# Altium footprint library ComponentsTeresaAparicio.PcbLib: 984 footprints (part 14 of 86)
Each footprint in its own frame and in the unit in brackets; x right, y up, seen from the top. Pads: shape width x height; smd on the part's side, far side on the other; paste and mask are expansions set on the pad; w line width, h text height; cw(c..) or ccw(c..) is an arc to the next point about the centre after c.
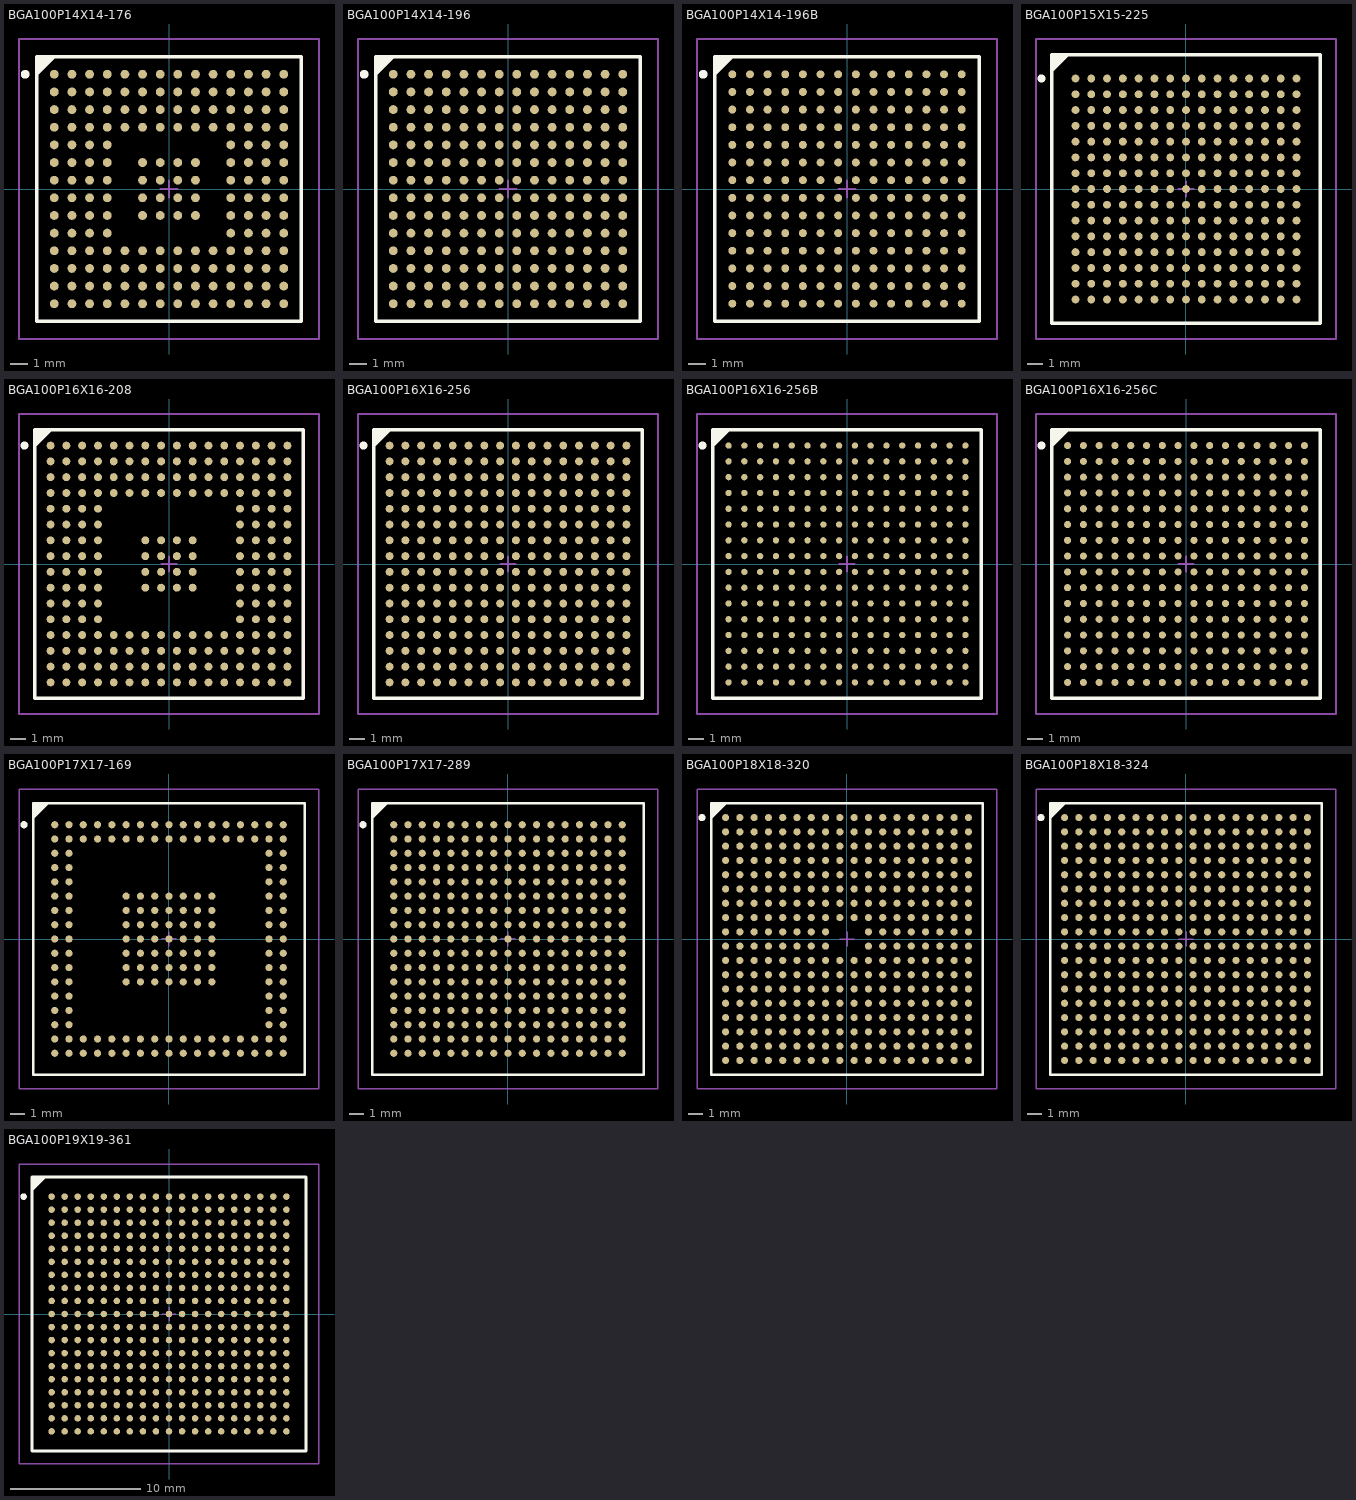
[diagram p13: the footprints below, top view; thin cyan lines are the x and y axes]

## BGA100P14X14-176 [mm] "BGA, 176-Leads, Body 15x15mm, Pitch 1mm"
height 2.05
pads (176):
  round 0.5 smd: A1(-6.5,6.5) A2(-5.5,6.5) A3(-4.5,6.5) A4(-3.5,6.5) A5(-2.5,6.5) A6(-1.5,6.5) A7(-0.5,6.5) A8(0.5,6.5) A9(1.5,6.5) A10(2.5,6.5) A11(3.5,6.5) A12(4.5,6.5) A13(5.5,6.5) A14(6.5,6.5) B1(-6.5,5.5) B2(-5.5,5.5) B3(-4.5,5.5) B4(-3.5,5.5) B5(-2.5,5.5) B6(-1.5,5.5) B7(-0.5,5.5) B8(0.5,5.5) B9(1.5,5.5) B10(2.5,5.5) B11(3.5,5.5) B12(4.5,5.5) B13(5.5,5.5) B14(6.5,5.5) C1(-6.5,4.5) C2(-5.5,4.5) C3(-4.5,4.5) C4(-3.5,4.5) C5(-2.5,4.5) C6(-1.5,4.5) C7(-0.5,4.5) C8(0.5,4.5) C9(1.5,4.5) C10(2.5,4.5) C11(3.5,4.5) C12(4.5,4.5) C13(5.5,4.5) C14(6.5,4.5) D1(-6.5,3.5) D2(-5.5,3.5) D3(-4.5,3.5) D4(-3.5,3.5) D5(-2.5,3.5) D6(-1.5,3.5) D7(-0.5,3.5) D8(0.5,3.5) D9(1.5,3.5) D10(2.5,3.5) D11(3.5,3.5) D12(4.5,3.5) D13(5.5,3.5) D14(6.5,3.5) E1(-6.5,2.5) E2(-5.5,2.5) E3(-4.5,2.5) E4(-3.5,2.5) E11(3.5,2.5) E12(4.5,2.5) E13(5.5,2.5) E14(6.5,2.5) F1(-6.5,1.5) F2(-5.5,1.5) F3(-4.5,1.5) F4(-3.5,1.5) F6(-1.5,1.5) F7(-0.5,1.5) F8(0.5,1.5) F9(1.5,1.5) F11(3.5,1.5) F12(4.5,1.5) F13(5.5,1.5) F14(6.5,1.5) G1(-6.5,0.5) G2(-5.5,0.5) G3(-4.5,0.5) G4(-3.5,0.5) G6(-1.5,0.5) G7(-0.5,0.5) G8(0.5,0.5) G9(1.5,0.5) G11(3.5,0.5) G12(4.5,0.5) G13(5.5,0.5) G14(6.5,0.5) H1(-6.5,-0.5) H2(-5.5,-0.5) H3(-4.5,-0.5) H4(-3.5,-0.5) H6(-1.5,-0.5) H7(-0.5,-0.5) H8(0.5,-0.5) H9(1.5,-0.5) H11(3.5,-0.5) H12(4.5,-0.5) H13(5.5,-0.5) H14(6.5,-0.5) J1(-6.5,-1.5) J2(-5.5,-1.5) J3(-4.5,-1.5) J4(-3.5,-1.5) J6(-1.5,-1.5) J7(-0.5,-1.5) J8(0.5,-1.5) J9(1.5,-1.5) J11(3.5,-1.5) J12(4.5,-1.5) J13(5.5,-1.5) J14(6.5,-1.5) K1(-6.5,-2.5) K2(-5.5,-2.5) K3(-4.5,-2.5) K4(-3.5,-2.5) K11(3.5,-2.5) K12(4.5,-2.5) K13(5.5,-2.5) K14(6.5,-2.5) L1(-6.5,-3.5) L2(-5.5,-3.5) L3(-4.5,-3.5) L4(-3.5,-3.5) L5(-2.5,-3.5) L6(-1.5,-3.5) L7(-0.5,-3.5) L8(0.5,-3.5) L9(1.5,-3.5) L10(2.5,-3.5) L11(3.5,-3.5) L12(4.5,-3.5) L13(5.5,-3.5) L14(6.5,-3.5) M1(-6.5,-4.5) M2(-5.5,-4.5) M3(-4.5,-4.5) M4(-3.5,-4.5) M5(-2.5,-4.5) M6(-1.5,-4.5) M7(-0.5,-4.5) M8(0.5,-4.5) M9(1.5,-4.5) M10(2.5,-4.5) M11(3.5,-4.5) M12(4.5,-4.5) M13(5.5,-4.5) M14(6.5,-4.5) N1(-6.5,-5.5) N2(-5.5,-5.5) N3(-4.5,-5.5) N4(-3.5,-5.5) N5(-2.5,-5.5) N6(-1.5,-5.5) N7(-0.5,-5.5) N8(0.5,-5.5) N9(1.5,-5.5) N10(2.5,-5.5) N11(3.5,-5.5) N12(4.5,-5.5) N13(5.5,-5.5) N14(6.5,-5.5) P1(-6.5,-6.5) P2(-5.5,-6.5) P3(-4.5,-6.5) P4(-3.5,-6.5) P5(-2.5,-6.5) P6(-1.5,-6.5) P7(-0.5,-6.5) P8(0.5,-6.5) P9(1.5,-6.5) P10(2.5,-6.5) P11(3.5,-6.5) P12(4.5,-6.5) P13(5.5,-6.5) P14(6.5,-6.5)
Top Overlay:
  circle w0.25: c-8.15,6.5 r0.125
  region: -6.5,7.5 -7.5,6.5 -7.5,7.5
  lines w0.2: -7.5,6.5 -6.5,7.5 ; -7.5,-7.5 -7.5,7.5 7.5,7.5 7.5,-7.5 -7.5,-7.5
Mechanical 13:
  lines w0.1: -7.5,-7.5 -7.5,7.5 7.5,7.5 7.5,-7.5 -7.5,-7.5
Mechanical 15:
  lines w0.1: -0.5,0 0.5,0 ; 0,-0.5 0,0.5 ; -8.5,-8.5 -8.5,8.5 8.5,8.5 8.5,-8.5 -8.5,-8.5
3D body: height 0, standoff 0, extent -7.5,-7.5 7.5,7.5

## BGA100P14X14-196 [mm] "BGA, 196-Leads, Body 15x15mm, Pitch 1mm"
height 1.9
pads (196):
  round 0.5 smd: A1(-6.5,6.5) A2(-5.5,6.5) A3(-4.5,6.5) A4(-3.5,6.5) A5(-2.5,6.5) A6(-1.5,6.5) A7(-0.5,6.5) A8(0.5,6.5) A9(1.5,6.5) A10(2.5,6.5) A11(3.5,6.5) A12(4.5,6.5) A13(5.5,6.5) A14(6.5,6.5) B1(-6.5,5.5) B2(-5.5,5.5) B3(-4.5,5.5) B4(-3.5,5.5) B5(-2.5,5.5) B6(-1.5,5.5) B7(-0.5,5.5) B8(0.5,5.5) B9(1.5,5.5) B10(2.5,5.5) B11(3.5,5.5) B12(4.5,5.5) B13(5.5,5.5) B14(6.5,5.5) C1(-6.5,4.5) C2(-5.5,4.5) C3(-4.5,4.5) C4(-3.5,4.5) C5(-2.5,4.5) C6(-1.5,4.5) C7(-0.5,4.5) C8(0.5,4.5) C9(1.5,4.5) C10(2.5,4.5) C11(3.5,4.5) C12(4.5,4.5) C13(5.5,4.5) C14(6.5,4.5) D1(-6.5,3.5) D2(-5.5,3.5) D3(-4.5,3.5) D4(-3.5,3.5) D5(-2.5,3.5) D6(-1.5,3.5) D7(-0.5,3.5) D8(0.5,3.5) D9(1.5,3.5) D10(2.5,3.5) D11(3.5,3.5) D12(4.5,3.5) D13(5.5,3.5) D14(6.5,3.5) E1(-6.5,2.5) E2(-5.5,2.5) E3(-4.5,2.5) E4(-3.5,2.5) E5(-2.5,2.5) E6(-1.5,2.5) E7(-0.5,2.5) E8(0.5,2.5) E9(1.5,2.5) E10(2.5,2.5) E11(3.5,2.5) E12(4.5,2.5) E13(5.5,2.5) E14(6.5,2.5) F1(-6.5,1.5) F2(-5.5,1.5) F3(-4.5,1.5) F4(-3.5,1.5) F5(-2.5,1.5) F6(-1.5,1.5) F7(-0.5,1.5) F8(0.5,1.5) F9(1.5,1.5) F10(2.5,1.5) F11(3.5,1.5) F12(4.5,1.5) F13(5.5,1.5) F14(6.5,1.5) G1(-6.5,0.5) G2(-5.5,0.5) G3(-4.5,0.5) G4(-3.5,0.5) G5(-2.5,0.5) G6(-1.5,0.5) G7(-0.5,0.5) G8(0.5,0.5) G9(1.5,0.5) G10(2.5,0.5) G11(3.5,0.5) G12(4.5,0.5) G13(5.5,0.5) G14(6.5,0.5) H1(-6.5,-0.5) H2(-5.5,-0.5) H3(-4.5,-0.5) H4(-3.5,-0.5) H5(-2.5,-0.5) H6(-1.5,-0.5) H7(-0.5,-0.5) H8(0.5,-0.5) H9(1.5,-0.5) H10(2.5,-0.5) H11(3.5,-0.5) H12(4.5,-0.5) H13(5.5,-0.5) H14(6.5,-0.5) J1(-6.5,-1.5) J2(-5.5,-1.5) J3(-4.5,-1.5) J4(-3.5,-1.5) J5(-2.5,-1.5) J6(-1.5,-1.5) J7(-0.5,-1.5) J8(0.5,-1.5) J9(1.5,-1.5) J10(2.5,-1.5) J11(3.5,-1.5) J12(4.5,-1.5) J13(5.5,-1.5) J14(6.5,-1.5) K1(-6.5,-2.5) K2(-5.5,-2.5) K3(-4.5,-2.5) K4(-3.5,-2.5) K5(-2.5,-2.5) K6(-1.5,-2.5) K7(-0.5,-2.5) K8(0.5,-2.5) K9(1.5,-2.5) K10(2.5,-2.5) K11(3.5,-2.5) K12(4.5,-2.5) K13(5.5,-2.5) K14(6.5,-2.5) L1(-6.5,-3.5) L2(-5.5,-3.5) L3(-4.5,-3.5) L4(-3.5,-3.5) L5(-2.5,-3.5) L6(-1.5,-3.5) L7(-0.5,-3.5) L8(0.5,-3.5) L9(1.5,-3.5) L10(2.5,-3.5) L11(3.5,-3.5) L12(4.5,-3.5) L13(5.5,-3.5) L14(6.5,-3.5) M1(-6.5,-4.5) M2(-5.5,-4.5) M3(-4.5,-4.5) M4(-3.5,-4.5) M5(-2.5,-4.5) M6(-1.5,-4.5) M7(-0.5,-4.5) M8(0.5,-4.5) M9(1.5,-4.5) M10(2.5,-4.5) M11(3.5,-4.5) M12(4.5,-4.5) M13(5.5,-4.5) M14(6.5,-4.5) N1(-6.5,-5.5) N2(-5.5,-5.5) N3(-4.5,-5.5) N4(-3.5,-5.5) N5(-2.5,-5.5) N6(-1.5,-5.5) N7(-0.5,-5.5) N8(0.5,-5.5) N9(1.5,-5.5) N10(2.5,-5.5) N11(3.5,-5.5) N12(4.5,-5.5) N13(5.5,-5.5) N14(6.5,-5.5) P1(-6.5,-6.5) P2(-5.5,-6.5) P3(-4.5,-6.5) P4(-3.5,-6.5) P5(-2.5,-6.5) P6(-1.5,-6.5) P7(-0.5,-6.5) P8(0.5,-6.5) P9(1.5,-6.5) P10(2.5,-6.5) P11(3.5,-6.5) P12(4.5,-6.5) P13(5.5,-6.5) P14(6.5,-6.5)
Top Overlay:
  circle w0.25: c-8.15,6.5 r0.125
  region: -6.5,7.5 -7.5,6.5 -7.5,7.5
  lines w0.2: -7.5,6.5 -6.5,7.5 ; -7.5,-7.5 -7.5,7.5 7.5,7.5 7.5,-7.5 -7.5,-7.5
Mechanical 13:
  lines w0.1: -7.5,-7.5 -7.5,7.5 7.5,7.5 7.5,-7.5 -7.5,-7.5
Mechanical 15:
  lines w0.1: -0.5,0 0.5,0 ; 0,-0.5 0,0.5 ; -8.5,-8.5 -8.5,8.5 8.5,8.5 8.5,-8.5 -8.5,-8.5
3D body: height 0, standoff 0, extent -7.5,-7.5 7.5,7.5

## BGA100P14X14-196B [mm] "BGA, 196-Leads, Body 15x15mm, Pitch 1mm"
height 1.7
pads (196):
  round 0.45 smd: A1(-6.5,6.5) A2(-5.5,6.5) A3(-4.5,6.5) A4(-3.5,6.5) A5(-2.5,6.5) A6(-1.5,6.5) A7(-0.5,6.5) A8(0.5,6.5) A9(1.5,6.5) A10(2.5,6.5) A11(3.5,6.5) A12(4.5,6.5) A13(5.5,6.5) A14(6.5,6.5) B1(-6.5,5.5) B2(-5.5,5.5) B3(-4.5,5.5) B4(-3.5,5.5) B5(-2.5,5.5) B6(-1.5,5.5) B7(-0.5,5.5) B8(0.5,5.5) B9(1.5,5.5) B10(2.5,5.5) B11(3.5,5.5) B12(4.5,5.5) B13(5.5,5.5) B14(6.5,5.5) C1(-6.5,4.5) C2(-5.5,4.5) C3(-4.5,4.5) C4(-3.5,4.5) C5(-2.5,4.5) C6(-1.5,4.5) C7(-0.5,4.5) C8(0.5,4.5) C9(1.5,4.5) C10(2.5,4.5) C11(3.5,4.5) C12(4.5,4.5) C13(5.5,4.5) C14(6.5,4.5) D1(-6.5,3.5) D2(-5.5,3.5) D3(-4.5,3.5) D4(-3.5,3.5) D5(-2.5,3.5) D6(-1.5,3.5) D7(-0.5,3.5) D8(0.5,3.5) D9(1.5,3.5) D10(2.5,3.5) D11(3.5,3.5) D12(4.5,3.5) D13(5.5,3.5) D14(6.5,3.5) E1(-6.5,2.5) E2(-5.5,2.5) E3(-4.5,2.5) E4(-3.5,2.5) E5(-2.5,2.5) E6(-1.5,2.5) E7(-0.5,2.5) E8(0.5,2.5) E9(1.5,2.5) E10(2.5,2.5) E11(3.5,2.5) E12(4.5,2.5) E13(5.5,2.5) E14(6.5,2.5) F1(-6.5,1.5) F2(-5.5,1.5) F3(-4.5,1.5) F4(-3.5,1.5) F5(-2.5,1.5) F6(-1.5,1.5) F7(-0.5,1.5) F8(0.5,1.5) F9(1.5,1.5) F10(2.5,1.5) F11(3.5,1.5) F12(4.5,1.5) F13(5.5,1.5) F14(6.5,1.5) G1(-6.5,0.5) G2(-5.5,0.5) G3(-4.5,0.5) G4(-3.5,0.5) G5(-2.5,0.5) G6(-1.5,0.5) G7(-0.5,0.5) G8(0.5,0.5) G9(1.5,0.5) G10(2.5,0.5) G11(3.5,0.5) G12(4.5,0.5) G13(5.5,0.5) G14(6.5,0.5) H1(-6.5,-0.5) H2(-5.5,-0.5) H3(-4.5,-0.5) H4(-3.5,-0.5) H5(-2.5,-0.5) H6(-1.5,-0.5) H7(-0.5,-0.5) H8(0.5,-0.5) H9(1.5,-0.5) H10(2.5,-0.5) H11(3.5,-0.5) H12(4.5,-0.5) H13(5.5,-0.5) H14(6.5,-0.5) J1(-6.5,-1.5) J2(-5.5,-1.5) J3(-4.5,-1.5) J4(-3.5,-1.5) J5(-2.5,-1.5) J6(-1.5,-1.5) J7(-0.5,-1.5) J8(0.5,-1.5) J9(1.5,-1.5) J10(2.5,-1.5) J11(3.5,-1.5) J12(4.5,-1.5) J13(5.5,-1.5) J14(6.5,-1.5) K1(-6.5,-2.5) K2(-5.5,-2.5) K3(-4.5,-2.5) K4(-3.5,-2.5) K5(-2.5,-2.5) K6(-1.5,-2.5) K7(-0.5,-2.5) K8(0.5,-2.5) K9(1.5,-2.5) K10(2.5,-2.5) K11(3.5,-2.5) K12(4.5,-2.5) K13(5.5,-2.5) K14(6.5,-2.5) L1(-6.5,-3.5) L2(-5.5,-3.5) L3(-4.5,-3.5) L4(-3.5,-3.5) L5(-2.5,-3.5) L6(-1.5,-3.5) L7(-0.5,-3.5) L8(0.5,-3.5) L9(1.5,-3.5) L10(2.5,-3.5) L11(3.5,-3.5) L12(4.5,-3.5) L13(5.5,-3.5) L14(6.5,-3.5) M1(-6.5,-4.5) M2(-5.5,-4.5) M3(-4.5,-4.5) M4(-3.5,-4.5) M5(-2.5,-4.5) M6(-1.5,-4.5) M7(-0.5,-4.5) M8(0.5,-4.5) M9(1.5,-4.5) M10(2.5,-4.5) M11(3.5,-4.5) M12(4.5,-4.5) M13(5.5,-4.5) M14(6.5,-4.5) N1(-6.5,-5.5) N2(-5.5,-5.5) N3(-4.5,-5.5) N4(-3.5,-5.5) N5(-2.5,-5.5) N6(-1.5,-5.5) N7(-0.5,-5.5) N8(0.5,-5.5) N9(1.5,-5.5) N10(2.5,-5.5) N11(3.5,-5.5) N12(4.5,-5.5) N13(5.5,-5.5) N14(6.5,-5.5) P1(-6.5,-6.5) P2(-5.5,-6.5) P3(-4.5,-6.5) P4(-3.5,-6.5) P5(-2.5,-6.5) P6(-1.5,-6.5) P7(-0.5,-6.5) P8(0.5,-6.5) P9(1.5,-6.5) P10(2.5,-6.5) P11(3.5,-6.5) P12(4.5,-6.5) P13(5.5,-6.5) P14(6.5,-6.5)
Top Overlay:
  circle w0.25: c-8.15,6.5 r0.125
  region: -6.5,7.5 -7.5,6.5 -7.5,7.5
  lines w0.2: -7.5,6.5 -6.5,7.5 ; -7.5,-7.5 -7.5,7.5 7.5,7.5 7.5,-7.5 -7.5,-7.5
Mechanical 13:
  lines w0.1: -7.5,-7.5 -7.5,7.5 7.5,7.5 7.5,-7.5 -7.5,-7.5
Mechanical 15:
  lines w0.1: -0.5,0 0.5,0 ; 0,-0.5 0,0.5 ; -8.5,-8.5 -8.5,8.5 8.5,8.5 8.5,-8.5 -8.5,-8.5
3D body: height 1.7, standoff 0, extent -7.5,-7.5 7.5,7.5

## BGA100P15X15-225 [mm] "BGA, 225-Leads, Body 17x17mm, Pitch 1mm"
height 3.5
pads (225):
  round 0.5 smd: A1(-7,7) A2(-6,7) A3(-5,7) A4(-4,7) A5(-3,7) A6(-2,7) A7(-1,7) A8(0,7) A9(1,7) A10(2,7) A11(3,7) A12(4,7) A13(5,7) A14(6,7) A15(7,7) B1(-7,6) B2(-6,6) B3(-5,6) B4(-4,6) B5(-3,6) B6(-2,6) B7(-1,6) B8(0,6) B9(1,6) B10(2,6) B11(3,6) B12(4,6) B13(5,6) B14(6,6) B15(7,6) C1(-7,5) C2(-6,5) C3(-5,5) C4(-4,5) C5(-3,5) C6(-2,5) C7(-1,5) C8(0,5) C9(1,5) C10(2,5) C11(3,5) C12(4,5) C13(5,5) C14(6,5) C15(7,5) D1(-7,4) D2(-6,4) D3(-5,4) D4(-4,4) D5(-3,4) D6(-2,4) D7(-1,4) D8(0,4) D9(1,4) D10(2,4) D11(3,4) D12(4,4) D13(5,4) D14(6,4) D15(7,4) E1(-7,3) E2(-6,3) E3(-5,3) E4(-4,3) E5(-3,3) E6(-2,3) E7(-1,3) E8(0,3) E9(1,3) E10(2,3) E11(3,3) E12(4,3) E13(5,3) E14(6,3) E15(7,3) F1(-7,2) F2(-6,2) F3(-5,2) F4(-4,2) F5(-3,2) F6(-2,2) F7(-1,2) F8(0,2) F9(1,2) F10(2,2) F11(3,2) F12(4,2) F13(5,2) F14(6,2) F15(7,2) G1(-7,1) G2(-6,1) G3(-5,1) G4(-4,1) G5(-3,1) G6(-2,1) G7(-1,1) G8(0,1) G9(1,1) G10(2,1) G11(3,1) G12(4,1) G13(5,1) G14(6,1) G15(7,1) H1(-7,0) H2(-6,0) H3(-5,0) H4(-4,0) H5(-3,0) H6(-2,0) H7(-1,0) H8(0,0) H9(1,0) H10(2,0) H11(3,0) H12(4,0) H13(5,0) H14(6,0) H15(7,0) J1(-7,-1) J2(-6,-1) J3(-5,-1) J4(-4,-1) J5(-3,-1) J6(-2,-1) J7(-1,-1) J8(0,-1) J9(1,-1) J10(2,-1) J11(3,-1) J12(4,-1) J13(5,-1) J14(6,-1) J15(7,-1) K1(-7,-2) K2(-6,-2) K3(-5,-2) K4(-4,-2) K5(-3,-2) K6(-2,-2) K7(-1,-2) K8(0,-2) K9(1,-2) K10(2,-2) K11(3,-2) K12(4,-2) K13(5,-2) K14(6,-2) K15(7,-2) L1(-7,-3) L2(-6,-3) L3(-5,-3) L4(-4,-3) L5(-3,-3) L6(-2,-3) L7(-1,-3) L8(0,-3) L9(1,-3) L10(2,-3) L11(3,-3) L12(4,-3) L13(5,-3) L14(6,-3) L15(7,-3) M1(-7,-4) M2(-6,-4) M3(-5,-4) M4(-4,-4) M5(-3,-4) M6(-2,-4) M7(-1,-4) M8(0,-4) M9(1,-4) M10(2,-4) M11(3,-4) M12(4,-4) M13(5,-4) M14(6,-4) M15(7,-4) N1(-7,-5) N2(-6,-5) N3(-5,-5) N4(-4,-5) N5(-3,-5) N6(-2,-5) N7(-1,-5) N8(0,-5) N9(1,-5) N10(2,-5) N11(3,-5) N12(4,-5) N13(5,-5) N14(6,-5) N15(7,-5) P1(-7,-6) P2(-6,-6) P3(-5,-6) P4(-4,-6) P5(-3,-6) P6(-2,-6) P7(-1,-6) P8(0,-6) P9(1,-6) P10(2,-6) P11(3,-6) P12(4,-6) P13(5,-6) P14(6,-6) P15(7,-6) R1(-7,-7) R2(-6,-7) R3(-5,-7) R4(-4,-7) R5(-3,-7) R6(-2,-7) R7(-1,-7) R8(0,-7) R9(1,-7) R10(2,-7) R11(3,-7) R12(4,-7) R13(5,-7) R14(6,-7) R15(7,-7)
Top Overlay:
  circle w0.25: c-9.15,7 r0.125
  region: -7.5,8.5 -8.5,7.5 -8.5,8.5
  lines w0.2: -8.5,7.5 -7.5,8.5 ; -8.5,-8.5 8.5,-8.5 8.5,8.5 -8.5,8.5 -8.5,-8.5
Mechanical 13:
  lines w0.1: -8.5,-8.5 8.5,-8.5 8.5,8.5 -8.5,8.5 -8.5,-8.5
Mechanical 15:
  lines w0.1: -0.5,0 0.5,0 ; 0,-0.5 0,0.5 ; -9.5,-9.5 9.5,-9.5 9.5,9.5 -9.5,9.5 -9.5,-9.5
3D body: height 0, standoff 0, extent -8.5,-8.5 8.5,8.5

## BGA100P16X16-208 [mm] "BGA, 208-Leads, Body 17x17mm, Pitch 1mm"
height 2.1
pads (208):
  round 0.5 smd: A1(-7.5,7.5) A2(-6.5,7.5) A3(-5.5,7.5) A4(-4.5,7.5) A5(-3.5,7.5) A6(-2.5,7.5) A7(-1.5,7.5) A8(-0.5,7.5) A9(0.5,7.5) A10(1.5,7.5) A11(2.5,7.5) A12(3.5,7.5) A13(4.5,7.5) A14(5.5,7.5) A15(6.5,7.5) A16(7.5,7.5) B1(-7.5,6.5) B2(-6.5,6.5) B3(-5.5,6.5) B4(-4.5,6.5) B5(-3.5,6.5) B6(-2.5,6.5) B7(-1.5,6.5) B8(-0.5,6.5) B9(0.5,6.5) B10(1.5,6.5) B11(2.5,6.5) B12(3.5,6.5) B13(4.5,6.5) B14(5.5,6.5) B15(6.5,6.5) B16(7.5,6.5) C1(-7.5,5.5) C2(-6.5,5.5) C3(-5.5,5.5) C4(-4.5,5.5) C5(-3.5,5.5) C6(-2.5,5.5) C7(-1.5,5.5) C8(-0.5,5.5) C9(0.5,5.5) C10(1.5,5.5) C11(2.5,5.5) C12(3.5,5.5) C13(4.5,5.5) C14(5.5,5.5) C15(6.5,5.5) C16(7.5,5.5) D1(-7.5,4.5) D2(-6.5,4.5) D3(-5.5,4.5) D4(-4.5,4.5) D5(-3.5,4.5) D6(-2.5,4.5) D7(-1.5,4.5) D8(-0.5,4.5) D9(0.5,4.5) D10(1.5,4.5) D11(2.5,4.5) D12(3.5,4.5) D13(4.5,4.5) D14(5.5,4.5) D15(6.5,4.5) D16(7.5,4.5) E1(-7.5,3.5) E2(-6.5,3.5) E3(-5.5,3.5) E4(-4.5,3.5) E13(4.5,3.5) E14(5.5,3.5) E15(6.5,3.5) E16(7.5,3.5) F1(-7.5,2.5) F2(-6.5,2.5) F3(-5.5,2.5) F4(-4.5,2.5) F13(4.5,2.5) F14(5.5,2.5) F15(6.5,2.5) F16(7.5,2.5) G1(-7.5,1.5) G2(-6.5,1.5) G3(-5.5,1.5) G4(-4.5,1.5) G7(-1.5,1.5) G8(-0.5,1.5) G9(0.5,1.5) G10(1.5,1.5) G13(4.5,1.5) G14(5.5,1.5) G15(6.5,1.5) G16(7.5,1.5) H1(-7.5,0.5) H2(-6.5,0.5) H3(-5.5,0.5) H4(-4.5,0.5) H7(-1.5,0.5) H8(-0.5,0.5) H9(0.5,0.5) H10(1.5,0.5) H13(4.5,0.5) H14(5.5,0.5) H15(6.5,0.5) H16(7.5,0.5) J1(-7.5,-0.5) J2(-6.5,-0.5) J3(-5.5,-0.5) J4(-4.5,-0.5) J7(-1.5,-0.5) J8(-0.5,-0.5) J9(0.5,-0.5) J10(1.5,-0.5) J13(4.5,-0.5) J14(5.5,-0.5) J15(6.5,-0.5) J16(7.5,-0.5) K1(-7.5,-1.5) K2(-6.5,-1.5) K3(-5.5,-1.5) K4(-4.5,-1.5) K7(-1.5,-1.5) K8(-0.5,-1.5) K9(0.5,-1.5) K10(1.5,-1.5) K13(4.5,-1.5) K14(5.5,-1.5) K15(6.5,-1.5) K16(7.5,-1.5) L1(-7.5,-2.5) L2(-6.5,-2.5) L3(-5.5,-2.5) L4(-4.5,-2.5) L13(4.5,-2.5) L14(5.5,-2.5) L15(6.5,-2.5) L16(7.5,-2.5) M1(-7.5,-3.5) M2(-6.5,-3.5) M3(-5.5,-3.5) M4(-4.5,-3.5) M13(4.5,-3.5) M14(5.5,-3.5) M15(6.5,-3.5) M16(7.5,-3.5) N1(-7.5,-4.5) N2(-6.5,-4.5) N3(-5.5,-4.5) N4(-4.5,-4.5) N5(-3.5,-4.5) N6(-2.5,-4.5) N7(-1.5,-4.5) N8(-0.5,-4.5) N9(0.5,-4.5) N10(1.5,-4.5) N11(2.5,-4.5) N12(3.5,-4.5) N13(4.5,-4.5) N14(5.5,-4.5) N15(6.5,-4.5) N16(7.5,-4.5) P1(-7.5,-5.5) P2(-6.5,-5.5) P3(-5.5,-5.5) P4(-4.5,-5.5) P5(-3.5,-5.5) P6(-2.5,-5.5) P7(-1.5,-5.5) P8(-0.5,-5.5) P9(0.5,-5.5) P10(1.5,-5.5) P11(2.5,-5.5) P12(3.5,-5.5) P13(4.5,-5.5) P14(5.5,-5.5) P15(6.5,-5.5) P16(7.5,-5.5) R1(-7.5,-6.5) R2(-6.5,-6.5) R3(-5.5,-6.5) R4(-4.5,-6.5) R5(-3.5,-6.5) R6(-2.5,-6.5) R7(-1.5,-6.5) R8(-0.5,-6.5) R9(0.5,-6.5) R10(1.5,-6.5) R11(2.5,-6.5) R12(3.5,-6.5) R13(4.5,-6.5) R14(5.5,-6.5) R15(6.5,-6.5) R16(7.5,-6.5) T1(-7.5,-7.5) T2(-6.5,-7.5) T3(-5.5,-7.5) T4(-4.5,-7.5) T5(-3.5,-7.5) T6(-2.5,-7.5) T7(-1.5,-7.5) T8(-0.5,-7.5) T9(0.5,-7.5) T10(1.5,-7.5) T11(2.5,-7.5) T12(3.5,-7.5) T13(4.5,-7.5) T14(5.5,-7.5) T15(6.5,-7.5) T16(7.5,-7.5)
Top Overlay:
  circle w0.25: c-9.15,7.5 r0.125
  region: -7.5,8.5 -8.5,7.5 -8.5,8.5
  lines w0.2: -8.5,7.5 -7.5,8.5 ; -8.5,-8.5 -8.5,8.5 8.5,8.5 8.5,-8.5 -8.5,-8.5
Mechanical 13:
  lines w0.1: -8.5,-8.5 -8.5,8.5 8.5,8.5 8.5,-8.5 -8.5,-8.5
Mechanical 15:
  lines w0.1: -0.5,0 0.5,0 ; 0,-0.5 0,0.5 ; -9.5,-9.5 -9.5,9.5 9.5,9.5 9.5,-9.5 -9.5,-9.5
3D body: height 0, standoff 0, extent -8.5,-8.5 8.5,8.5

## BGA100P16X16-256 [mm] "BGA, 256-Leads, Body 17x17mm, Pitch 1mm"
height 1.87
pads (256):
  round 0.5 smd: A1(-7.5,7.5) A2(-6.5,7.5) A3(-5.5,7.5) A4(-4.5,7.5) A5(-3.5,7.5) A6(-2.5,7.5) A7(-1.5,7.5) A8(-0.5,7.5) A9(0.5,7.5) A10(1.5,7.5) A11(2.5,7.5) A12(3.5,7.5) A13(4.5,7.5) A14(5.5,7.5) A15(6.5,7.5) A16(7.5,7.5) B1(-7.5,6.5) B2(-6.5,6.5) B3(-5.5,6.5) B4(-4.5,6.5) B5(-3.5,6.5) B6(-2.5,6.5) B7(-1.5,6.5) B8(-0.5,6.5) B9(0.5,6.5) B10(1.5,6.5) B11(2.5,6.5) B12(3.5,6.5) B13(4.5,6.5) B14(5.5,6.5) B15(6.5,6.5) B16(7.5,6.5) C1(-7.5,5.5) C2(-6.5,5.5) C3(-5.5,5.5) C4(-4.5,5.5) C5(-3.5,5.5) C6(-2.5,5.5) C7(-1.5,5.5) C8(-0.5,5.5) C9(0.5,5.5) C10(1.5,5.5) C11(2.5,5.5) C12(3.5,5.5) C13(4.5,5.5) C14(5.5,5.5) C15(6.5,5.5) C16(7.5,5.5) D1(-7.5,4.5) D2(-6.5,4.5) D3(-5.5,4.5) D4(-4.5,4.5) D5(-3.5,4.5) D6(-2.5,4.5) D7(-1.5,4.5) D8(-0.5,4.5) D9(0.5,4.5) D10(1.5,4.5) D11(2.5,4.5) D12(3.5,4.5) D13(4.5,4.5) D14(5.5,4.5) D15(6.5,4.5) D16(7.5,4.5) E1(-7.5,3.5) E2(-6.5,3.5) E3(-5.5,3.5) E4(-4.5,3.5) E5(-3.5,3.5) E6(-2.5,3.5) E7(-1.5,3.5) E8(-0.5,3.5) E9(0.5,3.5) E10(1.5,3.5) E11(2.5,3.5) E12(3.5,3.5) E13(4.5,3.5) E14(5.5,3.5) E15(6.5,3.5) E16(7.5,3.5) F1(-7.5,2.5) F2(-6.5,2.5) F3(-5.5,2.5) F4(-4.5,2.5) F5(-3.5,2.5) F6(-2.5,2.5) F7(-1.5,2.5) F8(-0.5,2.5) F9(0.5,2.5) F10(1.5,2.5) F11(2.5,2.5) F12(3.5,2.5) F13(4.5,2.5) F14(5.5,2.5) F15(6.5,2.5) F16(7.5,2.5) G1(-7.5,1.5) G2(-6.5,1.5) G3(-5.5,1.5) G4(-4.5,1.5) G5(-3.5,1.5) G6(-2.5,1.5) G7(-1.5,1.5) G8(-0.5,1.5) G9(0.5,1.5) G10(1.5,1.5) G11(2.5,1.5) G12(3.5,1.5) G13(4.5,1.5) G14(5.5,1.5) G15(6.5,1.5) G16(7.5,1.5) H1(-7.5,0.5) H2(-6.5,0.5) H3(-5.5,0.5) H4(-4.5,0.5) H5(-3.5,0.5) H6(-2.5,0.5) H7(-1.5,0.5) H8(-0.5,0.5) H9(0.5,0.5) H10(1.5,0.5) H11(2.5,0.5) H12(3.5,0.5) H13(4.5,0.5) H14(5.5,0.5) H15(6.5,0.5) H16(7.5,0.5) J1(-7.5,-0.5) J2(-6.5,-0.5) J3(-5.5,-0.5) J4(-4.5,-0.5) J5(-3.5,-0.5) J6(-2.5,-0.5) J7(-1.5,-0.5) J8(-0.5,-0.5) J9(0.5,-0.5) J10(1.5,-0.5) J11(2.5,-0.5) J12(3.5,-0.5) J13(4.5,-0.5) J14(5.5,-0.5) J15(6.5,-0.5) J16(7.5,-0.5) K1(-7.5,-1.5) K2(-6.5,-1.5) K3(-5.5,-1.5) K4(-4.5,-1.5) K5(-3.5,-1.5) K6(-2.5,-1.5) K7(-1.5,-1.5) K8(-0.5,-1.5) K9(0.5,-1.5) K10(1.5,-1.5) K11(2.5,-1.5) K12(3.5,-1.5) K13(4.5,-1.5) K14(5.5,-1.5) K15(6.5,-1.5) K16(7.5,-1.5) L1(-7.5,-2.5) L2(-6.5,-2.5) L3(-5.5,-2.5) L4(-4.5,-2.5) L5(-3.5,-2.5) L6(-2.5,-2.5) L7(-1.5,-2.5) L8(-0.5,-2.5) L9(0.5,-2.5) L10(1.5,-2.5) L11(2.5,-2.5) L12(3.5,-2.5) L13(4.5,-2.5) L14(5.5,-2.5) L15(6.5,-2.5) L16(7.5,-2.5) M1(-7.5,-3.5) M2(-6.5,-3.5) M3(-5.5,-3.5) M4(-4.5,-3.5) M5(-3.5,-3.5) M6(-2.5,-3.5) M7(-1.5,-3.5) M8(-0.5,-3.5) M9(0.5,-3.5) M10(1.5,-3.5) M11(2.5,-3.5) M12(3.5,-3.5) M13(4.5,-3.5) M14(5.5,-3.5) M15(6.5,-3.5) M16(7.5,-3.5) N1(-7.5,-4.5) N2(-6.5,-4.5) N3(-5.5,-4.5) N4(-4.5,-4.5) N5(-3.5,-4.5) N6(-2.5,-4.5) N7(-1.5,-4.5) N8(-0.5,-4.5) N9(0.5,-4.5) N10(1.5,-4.5) N11(2.5,-4.5) N12(3.5,-4.5) N13(4.5,-4.5) N14(5.5,-4.5) N15(6.5,-4.5) N16(7.5,-4.5) P1(-7.5,-5.5) P2(-6.5,-5.5) P3(-5.5,-5.5) P4(-4.5,-5.5) P5(-3.5,-5.5) P6(-2.5,-5.5) P7(-1.5,-5.5) P8(-0.5,-5.5) P9(0.5,-5.5) P10(1.5,-5.5) P11(2.5,-5.5) P12(3.5,-5.5) P13(4.5,-5.5) P14(5.5,-5.5) P15(6.5,-5.5) P16(7.5,-5.5) R1(-7.5,-6.5) R2(-6.5,-6.5) R3(-5.5,-6.5) R4(-4.5,-6.5) R5(-3.5,-6.5) R6(-2.5,-6.5) R7(-1.5,-6.5) R8(-0.5,-6.5) R9(0.5,-6.5) R10(1.5,-6.5) R11(2.5,-6.5) R12(3.5,-6.5) R13(4.5,-6.5) R14(5.5,-6.5) R15(6.5,-6.5) R16(7.5,-6.5) T1(-7.5,-7.5) T2(-6.5,-7.5) T3(-5.5,-7.5) T4(-4.5,-7.5) T5(-3.5,-7.5) T6(-2.5,-7.5) T7(-1.5,-7.5) T8(-0.5,-7.5) T9(0.5,-7.5) T10(1.5,-7.5) T11(2.5,-7.5) T12(3.5,-7.5) T13(4.5,-7.5) T14(5.5,-7.5) T15(6.5,-7.5) T16(7.5,-7.5)
Top Overlay:
  circle w0.25: c-9.15,7.5 r0.125
  region: -7.5,8.5 -8.5,7.5 -8.5,8.5
  lines w0.2: -8.5,7.5 -7.5,8.5 ; -8.5,-8.5 -8.5,8.5 8.5,8.5 8.5,-8.5 -8.5,-8.5
Mechanical 13:
  lines w0.1: -8.5,-8.5 -8.5,8.5 8.5,8.5 8.5,-8.5 -8.5,-8.5
Mechanical 15:
  lines w0.1: -0.5,0 0.5,0 ; 0,-0.5 0,0.5 ; -9.5,-9.5 -9.5,9.5 9.5,9.5 9.5,-9.5 -9.5,-9.5
3D body: height 0, standoff 0, extent -8.5,-8.5 8.5,8.5

## BGA100P16X16-256B [mm] "BGA, 256-Leads, Body 17x17mm, Pitch 1mm"
height 1.7
pads (256):
  round 0.4 smd: A1(-7.5,7.5) A2(-6.5,7.5) A3(-5.5,7.5) A4(-4.5,7.5) A5(-3.5,7.5) A6(-2.5,7.5) A7(-1.5,7.5) A8(-0.5,7.5) A9(0.5,7.5) A10(1.5,7.5) A11(2.5,7.5) A12(3.5,7.5) A13(4.5,7.5) A14(5.5,7.5) A15(6.5,7.5) A16(7.5,7.5) B1(-7.5,6.5) B2(-6.5,6.5) B3(-5.5,6.5) B4(-4.5,6.5) B5(-3.5,6.5) B6(-2.5,6.5) B7(-1.5,6.5) B8(-0.5,6.5) B9(0.5,6.5) B10(1.5,6.5) B11(2.5,6.5) B12(3.5,6.5) B13(4.5,6.5) B14(5.5,6.5) B15(6.5,6.5) B16(7.5,6.5) C1(-7.5,5.5) C2(-6.5,5.5) C3(-5.5,5.5) C4(-4.5,5.5) C5(-3.5,5.5) C6(-2.5,5.5) C7(-1.5,5.5) C8(-0.5,5.5) C9(0.5,5.5) C10(1.5,5.5) C11(2.5,5.5) C12(3.5,5.5) C13(4.5,5.5) C14(5.5,5.5) C15(6.5,5.5) C16(7.5,5.5) D1(-7.5,4.5) D2(-6.5,4.5) D3(-5.5,4.5) D4(-4.5,4.5) D5(-3.5,4.5) D6(-2.5,4.5) D7(-1.5,4.5) D8(-0.5,4.5) D9(0.5,4.5) D10(1.5,4.5) D11(2.5,4.5) D12(3.5,4.5) D13(4.5,4.5) D14(5.5,4.5) D15(6.5,4.5) D16(7.5,4.5) E1(-7.5,3.5) E2(-6.5,3.5) E3(-5.5,3.5) E4(-4.5,3.5) E5(-3.5,3.5) E6(-2.5,3.5) E7(-1.5,3.5) E8(-0.5,3.5) E9(0.5,3.5) E10(1.5,3.5) E11(2.5,3.5) E12(3.5,3.5) E13(4.5,3.5) E14(5.5,3.5) E15(6.5,3.5) E16(7.5,3.5) F1(-7.5,2.5) F2(-6.5,2.5) F3(-5.5,2.5) F4(-4.5,2.5) F5(-3.5,2.5) F6(-2.5,2.5) F7(-1.5,2.5) F8(-0.5,2.5) F9(0.5,2.5) F10(1.5,2.5) F11(2.5,2.5) F12(3.5,2.5) F13(4.5,2.5) F14(5.5,2.5) F15(6.5,2.5) F16(7.5,2.5) G1(-7.5,1.5) G2(-6.5,1.5) G3(-5.5,1.5) G4(-4.5,1.5) G5(-3.5,1.5) G6(-2.5,1.5) G7(-1.5,1.5) G8(-0.5,1.5) G9(0.5,1.5) G10(1.5,1.5) G11(2.5,1.5) G12(3.5,1.5) G13(4.5,1.5) G14(5.5,1.5) G15(6.5,1.5) G16(7.5,1.5) H1(-7.5,0.5) H2(-6.5,0.5) H3(-5.5,0.5) H4(-4.5,0.5) H5(-3.5,0.5) H6(-2.5,0.5) H7(-1.5,0.5) H8(-0.5,0.5) H9(0.5,0.5) H10(1.5,0.5) H11(2.5,0.5) H12(3.5,0.5) H13(4.5,0.5) H14(5.5,0.5) H15(6.5,0.5) H16(7.5,0.5) J1(-7.5,-0.5) J2(-6.5,-0.5) J3(-5.5,-0.5) J4(-4.5,-0.5) J5(-3.5,-0.5) J6(-2.5,-0.5) J7(-1.5,-0.5) J8(-0.5,-0.5) J9(0.5,-0.5) J10(1.5,-0.5) J11(2.5,-0.5) J12(3.5,-0.5) J13(4.5,-0.5) J14(5.5,-0.5) J15(6.5,-0.5) J16(7.5,-0.5) K1(-7.5,-1.5) K2(-6.5,-1.5) K3(-5.5,-1.5) K4(-4.5,-1.5) K5(-3.5,-1.5) K6(-2.5,-1.5) K7(-1.5,-1.5) K8(-0.5,-1.5) K9(0.5,-1.5) K10(1.5,-1.5) K11(2.5,-1.5) K12(3.5,-1.5) K13(4.5,-1.5) K14(5.5,-1.5) K15(6.5,-1.5) K16(7.5,-1.5) L1(-7.5,-2.5) L2(-6.5,-2.5) L3(-5.5,-2.5) L4(-4.5,-2.5) L5(-3.5,-2.5) L6(-2.5,-2.5) L7(-1.5,-2.5) L8(-0.5,-2.5) L9(0.5,-2.5) L10(1.5,-2.5) L11(2.5,-2.5) L12(3.5,-2.5) L13(4.5,-2.5) L14(5.5,-2.5) L15(6.5,-2.5) L16(7.5,-2.5) M1(-7.5,-3.5) M2(-6.5,-3.5) M3(-5.5,-3.5) M4(-4.5,-3.5) M5(-3.5,-3.5) M6(-2.5,-3.5) M7(-1.5,-3.5) M8(-0.5,-3.5) M9(0.5,-3.5) M10(1.5,-3.5) M11(2.5,-3.5) M12(3.5,-3.5) M13(4.5,-3.5) M14(5.5,-3.5) M15(6.5,-3.5) M16(7.5,-3.5) N1(-7.5,-4.5) N2(-6.5,-4.5) N3(-5.5,-4.5) N4(-4.5,-4.5) N5(-3.5,-4.5) N6(-2.5,-4.5) N7(-1.5,-4.5) N8(-0.5,-4.5) N9(0.5,-4.5) N10(1.5,-4.5) N11(2.5,-4.5) N12(3.5,-4.5) N13(4.5,-4.5) N14(5.5,-4.5) N15(6.5,-4.5) N16(7.5,-4.5) P1(-7.5,-5.5) P2(-6.5,-5.5) P3(-5.5,-5.5) P4(-4.5,-5.5) P5(-3.5,-5.5) P6(-2.5,-5.5) P7(-1.5,-5.5) P8(-0.5,-5.5) P9(0.5,-5.5) P10(1.5,-5.5) P11(2.5,-5.5) P12(3.5,-5.5) P13(4.5,-5.5) P14(5.5,-5.5) P15(6.5,-5.5) P16(7.5,-5.5) R1(-7.5,-6.5) R2(-6.5,-6.5) R3(-5.5,-6.5) R4(-4.5,-6.5) R5(-3.5,-6.5) R6(-2.5,-6.5) R7(-1.5,-6.5) R8(-0.5,-6.5) R9(0.5,-6.5) R10(1.5,-6.5) R11(2.5,-6.5) R12(3.5,-6.5) R13(4.5,-6.5) R14(5.5,-6.5) R15(6.5,-6.5) R16(7.5,-6.5) T1(-7.5,-7.5) T2(-6.5,-7.5) T3(-5.5,-7.5) T4(-4.5,-7.5) T5(-3.5,-7.5) T6(-2.5,-7.5) T7(-1.5,-7.5) T8(-0.5,-7.5) T9(0.5,-7.5) T10(1.5,-7.5) T11(2.5,-7.5) T12(3.5,-7.5) T13(4.5,-7.5) T14(5.5,-7.5) T15(6.5,-7.5) T16(7.5,-7.5)
Top Overlay:
  circle w0.25: c-9.15,7.5 r0.125
  region: -7.5,8.5 -8.5,7.5 -8.5,8.5
  lines w0.2: -8.5,7.5 -7.5,8.5 ; -8.5,-8.5 8.5,-8.5 8.5,8.5 -8.5,8.5 -8.5,-8.5
Mechanical 13:
  lines w0.1: -8.5,-8.5 8.5,-8.5 8.5,8.5 -8.5,8.5 -8.5,-8.5
Mechanical 15:
  lines w0.1: -0.5,0 0.5,0 ; 0,-0.5 0,0.5 ; -9.5,-9.5 9.5,-9.5 9.5,9.5 -9.5,9.5 -9.5,-9.5
3D body: height 0, standoff 0, extent -8.5,-8.5 8.5,8.5

## BGA100P16X16-256C [mm] "BGA, 256-Leads, Body 17x17mm, Pitch 1mm"
height 1.97
pads (256):
  round 0.45 smd: A1(-7.5,7.5) A2(-6.5,7.5) A3(-5.5,7.5) A4(-4.5,7.5) A5(-3.5,7.5) A6(-2.5,7.5) A7(-1.5,7.5) A8(-0.5,7.5) A9(0.5,7.5) A10(1.5,7.5) A11(2.5,7.5) A12(3.5,7.5) A13(4.5,7.5) A14(5.5,7.5) A15(6.5,7.5) A16(7.5,7.5) B1(-7.5,6.5) B2(-6.5,6.5) B3(-5.5,6.5) B4(-4.5,6.5) B5(-3.5,6.5) B6(-2.5,6.5) B7(-1.5,6.5) B8(-0.5,6.5) B9(0.5,6.5) B10(1.5,6.5) B11(2.5,6.5) B12(3.5,6.5) B13(4.5,6.5) B14(5.5,6.5) B15(6.5,6.5) B16(7.5,6.5) C1(-7.5,5.5) C2(-6.5,5.5) C3(-5.5,5.5) C4(-4.5,5.5) C5(-3.5,5.5) C6(-2.5,5.5) C7(-1.5,5.5) C8(-0.5,5.5) C9(0.5,5.5) C10(1.5,5.5) C11(2.5,5.5) C12(3.5,5.5) C13(4.5,5.5) C14(5.5,5.5) C15(6.5,5.5) C16(7.5,5.5) D1(-7.5,4.5) D2(-6.5,4.5) D3(-5.5,4.5) D4(-4.5,4.5) D5(-3.5,4.5) D6(-2.5,4.5) D7(-1.5,4.5) D8(-0.5,4.5) D9(0.5,4.5) D10(1.5,4.5) D11(2.5,4.5) D12(3.5,4.5) D13(4.5,4.5) D14(5.5,4.5) D15(6.5,4.5) D16(7.5,4.5) E1(-7.5,3.5) E2(-6.5,3.5) E3(-5.5,3.5) E4(-4.5,3.5) E5(-3.5,3.5) E6(-2.5,3.5) E7(-1.5,3.5) E8(-0.5,3.5) E9(0.5,3.5) E10(1.5,3.5) E11(2.5,3.5) E12(3.5,3.5) E13(4.5,3.5) E14(5.5,3.5) E15(6.5,3.5) E16(7.5,3.5) F1(-7.5,2.5) F2(-6.5,2.5) F3(-5.5,2.5) F4(-4.5,2.5) F5(-3.5,2.5) F6(-2.5,2.5) F7(-1.5,2.5) F8(-0.5,2.5) F9(0.5,2.5) F10(1.5,2.5) F11(2.5,2.5) F12(3.5,2.5) F13(4.5,2.5) F14(5.5,2.5) F15(6.5,2.5) F16(7.5,2.5) G1(-7.5,1.5) G2(-6.5,1.5) G3(-5.5,1.5) G4(-4.5,1.5) G5(-3.5,1.5) G6(-2.5,1.5) G7(-1.5,1.5) G8(-0.5,1.5) G9(0.5,1.5) G10(1.5,1.5) G11(2.5,1.5) G12(3.5,1.5) G13(4.5,1.5) G14(5.5,1.5) G15(6.5,1.5) G16(7.5,1.5) H1(-7.5,0.5) H2(-6.5,0.5) H3(-5.5,0.5) H4(-4.5,0.5) H5(-3.5,0.5) H6(-2.5,0.5) H7(-1.5,0.5) H8(-0.5,0.5) H9(0.5,0.5) H10(1.5,0.5) H11(2.5,0.5) H12(3.5,0.5) H13(4.5,0.5) H14(5.5,0.5) H15(6.5,0.5) H16(7.5,0.5) J1(-7.5,-0.5) J2(-6.5,-0.5) J3(-5.5,-0.5) J4(-4.5,-0.5) J5(-3.5,-0.5) J6(-2.5,-0.5) J7(-1.5,-0.5) J8(-0.5,-0.5) J9(0.5,-0.5) J10(1.5,-0.5) J11(2.5,-0.5) J12(3.5,-0.5) J13(4.5,-0.5) J14(5.5,-0.5) J15(6.5,-0.5) J16(7.5,-0.5) K1(-7.5,-1.5) K2(-6.5,-1.5) K3(-5.5,-1.5) K4(-4.5,-1.5) K5(-3.5,-1.5) K6(-2.5,-1.5) K7(-1.5,-1.5) K8(-0.5,-1.5) K9(0.5,-1.5) K10(1.5,-1.5) K11(2.5,-1.5) K12(3.5,-1.5) K13(4.5,-1.5) K14(5.5,-1.5) K15(6.5,-1.5) K16(7.5,-1.5) L1(-7.5,-2.5) L2(-6.5,-2.5) L3(-5.5,-2.5) L4(-4.5,-2.5) L5(-3.5,-2.5) L6(-2.5,-2.5) L7(-1.5,-2.5) L8(-0.5,-2.5) L9(0.5,-2.5) L10(1.5,-2.5) L11(2.5,-2.5) L12(3.5,-2.5) L13(4.5,-2.5) L14(5.5,-2.5) L15(6.5,-2.5) L16(7.5,-2.5) M1(-7.5,-3.5) M2(-6.5,-3.5) M3(-5.5,-3.5) M4(-4.5,-3.5) M5(-3.5,-3.5) M6(-2.5,-3.5) M7(-1.5,-3.5) M8(-0.5,-3.5) M9(0.5,-3.5) M10(1.5,-3.5) M11(2.5,-3.5) M12(3.5,-3.5) M13(4.5,-3.5) M14(5.5,-3.5) M15(6.5,-3.5) M16(7.5,-3.5) N1(-7.5,-4.5) N2(-6.5,-4.5) N3(-5.5,-4.5) N4(-4.5,-4.5) N5(-3.5,-4.5) N6(-2.5,-4.5) N7(-1.5,-4.5) N8(-0.5,-4.5) N9(0.5,-4.5) N10(1.5,-4.5) N11(2.5,-4.5) N12(3.5,-4.5) N13(4.5,-4.5) N14(5.5,-4.5) N15(6.5,-4.5) N16(7.5,-4.5) P1(-7.5,-5.5) P2(-6.5,-5.5) P3(-5.5,-5.5) P4(-4.5,-5.5) P5(-3.5,-5.5) P6(-2.5,-5.5) P7(-1.5,-5.5) P8(-0.5,-5.5) P9(0.5,-5.5) P10(1.5,-5.5) P11(2.5,-5.5) P12(3.5,-5.5) P13(4.5,-5.5) P14(5.5,-5.5) P15(6.5,-5.5) P16(7.5,-5.5) R1(-7.5,-6.5) R2(-6.5,-6.5) R3(-5.5,-6.5) R4(-4.5,-6.5) R5(-3.5,-6.5) R6(-2.5,-6.5) R7(-1.5,-6.5) R8(-0.5,-6.5) R9(0.5,-6.5) R10(1.5,-6.5) R11(2.5,-6.5) R12(3.5,-6.5) R13(4.5,-6.5) R14(5.5,-6.5) R15(6.5,-6.5) R16(7.5,-6.5) T1(-7.5,-7.5) T2(-6.5,-7.5) T3(-5.5,-7.5) T4(-4.5,-7.5) T5(-3.5,-7.5) T6(-2.5,-7.5) T7(-1.5,-7.5) T8(-0.5,-7.5) T9(0.5,-7.5) T10(1.5,-7.5) T11(2.5,-7.5) T12(3.5,-7.5) T13(4.5,-7.5) T14(5.5,-7.5) T15(6.5,-7.5) T16(7.5,-7.5)
Top Overlay:
  circle w0.25: c-9.15,7.5 r0.125
  region: -7.5,8.5 -8.5,7.5 -8.5,8.5
  lines w0.2: -8.5,7.5 -7.5,8.5 ; -8.5,-8.5 -8.5,8.5 8.5,8.5 8.5,-8.5 -8.5,-8.5
Mechanical 13:
  lines w0.1: -8.5,-8.5 -8.5,8.5 8.5,8.5 8.5,-8.5 -8.5,-8.5
Mechanical 15:
  lines w0.1: -0.5,0 0.5,0 ; 0,-0.5 0,0.5 ; -9.5,-9.5 -9.5,9.5 9.5,9.5 9.5,-9.5 -9.5,-9.5
3D body: height 0, standoff 0, extent -8.5,-8.5 8.5,8.5

## BGA100P17X17-169 [mm] "BGA, 169-Leads, Body 19x19mm, Pitch 1mm"
height 2.5
pads (169):
  round 0.5 smd: A1(-8,8) A2(-7,8) A3(-6,8) A4(-5,8) A5(-4,8) A6(-3,8) A7(-2,8) A8(-1,8) A9(0,8) A10(1,8) A11(2,8) A12(3,8) A13(4,8) A14(5,8) A15(6,8) A16(7,8) A17(8,8) B1(-8,7) B2(-7,7) B3(-6,7) B4(-5,7) B5(-4,7) B6(-3,7) B7(-2,7) B8(-1,7) B9(0,7) B10(1,7) B11(2,7) B12(3,7) B13(4,7) B14(5,7) B15(6,7) B16(7,7) B17(8,7) C1(-8,6) C2(-7,6) C16(7,6) C17(8,6) D1(-8,5) D2(-7,5) D16(7,5) D17(8,5) E1(-8,4) E2(-7,4) E16(7,4) E17(8,4) F1(-8,3) F2(-7,3) F6(-3,3) F7(-2,3) F8(-1,3) F9(0,3) F10(1,3) F11(2,3) F12(3,3) F16(7,3) F17(8,3) G1(-8,2) G2(-7,2) G6(-3,2) G7(-2,2) G8(-1,2) G9(0,2) G10(1,2) G11(2,2) G12(3,2) G16(7,2) G17(8,2) H1(-8,1) H2(-7,1) H6(-3,1) H7(-2,1) H8(-1,1) H9(0,1) H10(1,1) H11(2,1) H12(3,1) H16(7,1) H17(8,1) J1(-8,0) J2(-7,0) J6(-3,0) J7(-2,0) J8(-1,0) J9(0,0) J10(1,0) J11(2,0) J12(3,0) J16(7,0) J17(8,0) K1(-8,-1) K2(-7,-1) K6(-3,-1) K7(-2,-1) K8(-1,-1) K9(0,-1) K10(1,-1) K11(2,-1) K12(3,-1) K16(7,-1) K17(8,-1) L1(-8,-2) L2(-7,-2) L6(-3,-2) L7(-2,-2) L8(-1,-2) L9(0,-2) L10(1,-2) L11(2,-2) L12(3,-2) L16(7,-2) L17(8,-2) M1(-8,-3) M2(-7,-3) M6(-3,-3) M7(-2,-3) M8(-1,-3) M9(0,-3) M10(1,-3) M11(2,-3) M12(3,-3) M16(7,-3) M17(8,-3) N1(-8,-4) N2(-7,-4) N16(7,-4) N17(8,-4) P1(-8,-5) P2(-7,-5) P16(7,-5) P17(8,-5) R1(-8,-6) R2(-7,-6) R16(7,-6) R17(8,-6) T1(-8,-7) T2(-7,-7) T3(-6,-7) T4(-5,-7) T5(-4,-7) T6(-3,-7) T7(-2,-7) T8(-1,-7) T9(0,-7) T10(1,-7) T11(2,-7) T12(3,-7) T13(4,-7) T14(5,-7) T15(6,-7) T16(7,-7) T17(8,-7) U1(-8,-8) U2(-7,-8) U3(-6,-8) U4(-5,-8) U5(-4,-8) U6(-3,-8) U7(-2,-8) U8(-1,-8) U9(0,-8) U10(1,-8) U11(2,-8) U12(3,-8) U13(4,-8) U14(5,-8) U15(6,-8) U16(7,-8) U17(8,-8)
Top Overlay:
  circle w0.25: c-10.15,8 r0.125
  region: -8.5,9.5 -9.5,8.5 -9.5,9.5
  lines w0.2: -9.5,8.5 -8.5,9.5 ; -9.5,-9.5 9.5,-9.5 9.5,9.5 -9.5,9.5 -9.5,-9.5
Mechanical 13:
  lines w0.1: -9.5,-9.5 9.5,-9.5 9.5,9.5 -9.5,9.5 -9.5,-9.5
Mechanical 15:
  lines w0.1: -0.5,0 0.5,0 ; 0,-0.5 0,0.5 ; -10.5,-10.5 10.5,-10.5 10.5,10.5 -10.5,10.5 -10.5,-10.5
3D body: height 0, standoff 0, extent -9.5,-9.5 9.5,9.5

## BGA100P17X17-289 [mm] "BGA, 289-Leads, Body 19x19mm, Pitch 1mm"
height 3.5
pads (289):
  round 0.5 smd: A1(-8,8) A2(-7,8) A3(-6,8) A4(-5,8) A5(-4,8) A6(-3,8) A7(-2,8) A8(-1,8) A9(0,8) A10(1,8) A11(2,8) A12(3,8) A13(4,8) A14(5,8) A15(6,8) A16(7,8) A17(8,8) B1(-8,7) B2(-7,7) B3(-6,7) B4(-5,7) B5(-4,7) B6(-3,7) B7(-2,7) B8(-1,7) B9(0,7) B10(1,7) B11(2,7) B12(3,7) B13(4,7) B14(5,7) B15(6,7) B16(7,7) B17(8,7) C1(-8,6) C2(-7,6) C3(-6,6) C4(-5,6) C5(-4,6) C6(-3,6) C7(-2,6) C8(-1,6) C9(0,6) C10(1,6) C11(2,6) C12(3,6) C13(4,6) C14(5,6) C15(6,6) C16(7,6) C17(8,6) D1(-8,5) D2(-7,5) D3(-6,5) D4(-5,5) D5(-4,5) D6(-3,5) D7(-2,5) D8(-1,5) D9(0,5) D10(1,5) D11(2,5) D12(3,5) D13(4,5) D14(5,5) D15(6,5) D16(7,5) D17(8,5) E1(-8,4) E2(-7,4) E3(-6,4) E4(-5,4) E5(-4,4) E6(-3,4) E7(-2,4) E8(-1,4) E9(0,4) E10(1,4) E11(2,4) E12(3,4) E13(4,4) E14(5,4) E15(6,4) E16(7,4) E17(8,4) F1(-8,3) F2(-7,3) F3(-6,3) F4(-5,3) F5(-4,3) F6(-3,3) F7(-2,3) F8(-1,3) F9(0,3) F10(1,3) F11(2,3) F12(3,3) F13(4,3) F14(5,3) F15(6,3) F16(7,3) F17(8,3) G1(-8,2) G2(-7,2) G3(-6,2) G4(-5,2) G5(-4,2) G6(-3,2) G7(-2,2) G8(-1,2) G9(0,2) G10(1,2) G11(2,2) G12(3,2) G13(4,2) G14(5,2) G15(6,2) G16(7,2) G17(8,2) H1(-8,1) H2(-7,1) H3(-6,1) H4(-5,1) H5(-4,1) H6(-3,1) H7(-2,1) H8(-1,1) H9(0,1) H10(1,1) H11(2,1) H12(3,1) H13(4,1) H14(5,1) H15(6,1) H16(7,1) H17(8,1) J1(-8,0) J2(-7,0) J3(-6,0) J4(-5,0) J5(-4,0) J6(-3,0) J7(-2,0) J8(-1,0) J9(0,0) J10(1,0) J11(2,0) J12(3,0) J13(4,0) J14(5,0) J15(6,0) J16(7,0) J17(8,0) K1(-8,-1) K2(-7,-1) K3(-6,-1) K4(-5,-1) K5(-4,-1) K6(-3,-1) K7(-2,-1) K8(-1,-1) K9(0,-1) K10(1,-1) K11(2,-1) K12(3,-1) K13(4,-1) K14(5,-1) K15(6,-1) K16(7,-1) K17(8,-1) L1(-8,-2) L2(-7,-2) L3(-6,-2) L4(-5,-2) L5(-4,-2) L6(-3,-2) L7(-2,-2) L8(-1,-2) L9(0,-2) L10(1,-2) L11(2,-2) L12(3,-2) L13(4,-2) L14(5,-2) L15(6,-2) L16(7,-2) L17(8,-2) M1(-8,-3) M2(-7,-3) M3(-6,-3) M4(-5,-3) M5(-4,-3) M6(-3,-3) M7(-2,-3) M8(-1,-3) M9(0,-3) M10(1,-3) M11(2,-3) M12(3,-3) M13(4,-3) M14(5,-3) M15(6,-3) M16(7,-3) M17(8,-3) N1(-8,-4) N2(-7,-4) N3(-6,-4) N4(-5,-4) N5(-4,-4) N6(-3,-4) N7(-2,-4) N8(-1,-4) N9(0,-4) N10(1,-4) N11(2,-4) N12(3,-4) N13(4,-4) N14(5,-4) N15(6,-4) N16(7,-4) N17(8,-4) P1(-8,-5) P2(-7,-5) P3(-6,-5) P4(-5,-5) P5(-4,-5) P6(-3,-5) P7(-2,-5) P8(-1,-5) P9(0,-5) P10(1,-5) P11(2,-5) P12(3,-5) P13(4,-5) P14(5,-5) P15(6,-5) P16(7,-5) P17(8,-5) R1(-8,-6) R2(-7,-6) R3(-6,-6) R4(-5,-6) R5(-4,-6) R6(-3,-6) R7(-2,-6) R8(-1,-6) R9(0,-6) R10(1,-6) R11(2,-6) R12(3,-6) R13(4,-6) R14(5,-6) R15(6,-6) R16(7,-6) R17(8,-6) T1(-8,-7) T2(-7,-7) T3(-6,-7) T4(-5,-7) T5(-4,-7) T6(-3,-7) T7(-2,-7) T8(-1,-7) T9(0,-7) T10(1,-7) T11(2,-7) T12(3,-7) T13(4,-7) T14(5,-7) T15(6,-7) T16(7,-7) T17(8,-7) U1(-8,-8) U2(-7,-8) U3(-6,-8) U4(-5,-8) U5(-4,-8) U6(-3,-8) U7(-2,-8) U8(-1,-8) U9(0,-8) U10(1,-8) U11(2,-8) U12(3,-8) U13(4,-8) U14(5,-8) U15(6,-8) U16(7,-8) U17(8,-8)
Top Overlay:
  circle w0.25: c-10.15,8 r0.125
  region: -8.5,9.5 -9.5,8.5 -9.5,9.5
  lines w0.2: -9.5,8.5 -8.5,9.5 ; -9.5,-9.5 -9.5,9.5 9.5,9.5 9.5,-9.5 -9.5,-9.5
Mechanical 13:
  lines w0.1: -9.5,-9.5 -9.5,9.5 9.5,9.5 9.5,-9.5 -9.5,-9.5
Mechanical 15:
  lines w0.1: -0.5,0 0.5,0 ; 0,-0.5 0,0.5 ; -10.5,-10.5 -10.5,10.5 10.5,10.5 10.5,-10.5 -10.5,-10.5
3D body: height 0, standoff 0, extent -9.5,-9.5 9.5,9.5

## BGA100P18X18-320 [mm] "320-Ball Fine Pitch Ball Grid Array (FG320)"
height 2
pads (320):
  round 0.5 smd: A1(-8.5,8.5) A2(-7.5,8.5) A3(-6.5,8.5) A4(-5.5,8.5) A5(-4.5,8.5) A6(-3.5,8.5) A7(-2.5,8.5) A8(-1.5,8.5) A9(-0.5,8.5) A10(0.5,8.5) A11(1.5,8.5) A12(2.5,8.5) A13(3.5,8.5) A14(4.5,8.5) A15(5.5,8.5) A16(6.5,8.5) A17(7.5,8.5) A18(8.5,8.5) B1(-8.5,7.5) B2(-7.5,7.5) B3(-6.5,7.5) B4(-5.5,7.5) B5(-4.5,7.5) B6(-3.5,7.5) B7(-2.5,7.5) B8(-1.5,7.5) B9(-0.5,7.5) B10(0.5,7.5) B11(1.5,7.5) B12(2.5,7.5) B13(3.5,7.5) B14(4.5,7.5) B15(5.5,7.5) B16(6.5,7.5) B17(7.5,7.5) B18(8.5,7.5) C1(-8.5,6.5) C2(-7.5,6.5) C3(-6.5,6.5) C4(-5.5,6.5) C5(-4.5,6.5) C6(-3.5,6.5) C7(-2.5,6.5) C8(-1.5,6.5) C9(-0.5,6.5) C10(0.5,6.5) C11(1.5,6.5) C12(2.5,6.5) C13(3.5,6.5) C14(4.5,6.5) C15(5.5,6.5) C16(6.5,6.5) C17(7.5,6.5) C18(8.5,6.5) D1(-8.5,5.5) D2(-7.5,5.5) D3(-6.5,5.5) D4(-5.5,5.5) D5(-4.5,5.5) D6(-3.5,5.5) D7(-2.5,5.5) D8(-1.5,5.5) D9(-0.5,5.5) D10(0.5,5.5) D11(1.5,5.5) D12(2.5,5.5) D13(3.5,5.5) D14(4.5,5.5) D15(5.5,5.5) D16(6.5,5.5) D17(7.5,5.5) D18(8.5,5.5) E1(-8.5,4.5) E2(-7.5,4.5) E3(-6.5,4.5) E4(-5.5,4.5) E5(-4.5,4.5) E6(-3.5,4.5) E7(-2.5,4.5) E8(-1.5,4.5) E9(-0.5,4.5) E10(0.5,4.5) E11(1.5,4.5) E12(2.5,4.5) E13(3.5,4.5) E14(4.5,4.5) E15(5.5,4.5) E16(6.5,4.5) E17(7.5,4.5) E18(8.5,4.5) F1(-8.5,3.5) F2(-7.5,3.5) F3(-6.5,3.5) F4(-5.5,3.5) F5(-4.5,3.5) F6(-3.5,3.5) F7(-2.5,3.5) F8(-1.5,3.5) F9(-0.5,3.5) F10(0.5,3.5) F11(1.5,3.5) F12(2.5,3.5) F13(3.5,3.5) F14(4.5,3.5) F15(5.5,3.5) F16(6.5,3.5) F17(7.5,3.5) F18(8.5,3.5) G1(-8.5,2.5) G2(-7.5,2.5) G3(-6.5,2.5) G4(-5.5,2.5) G5(-4.5,2.5) G6(-3.5,2.5) G7(-2.5,2.5) G8(-1.5,2.5) G9(-0.5,2.5) G10(0.5,2.5) G11(1.5,2.5) G12(2.5,2.5) G13(3.5,2.5) G14(4.5,2.5) G15(5.5,2.5) G16(6.5,2.5) G17(7.5,2.5) G18(8.5,2.5) H1(-8.5,1.5) H2(-7.5,1.5) H3(-6.5,1.5) H4(-5.5,1.5) H5(-4.5,1.5) H6(-3.5,1.5) H7(-2.5,1.5) H8(-1.5,1.5) H9(-0.5,1.5) H10(0.5,1.5) H11(1.5,1.5) H12(2.5,1.5) H13(3.5,1.5) H14(4.5,1.5) H15(5.5,1.5) H16(6.5,1.5) H17(7.5,1.5) H18(8.5,1.5) J1(-8.5,0.5) J2(-7.5,0.5) J3(-6.5,0.5) J4(-5.5,0.5) J5(-4.5,0.5) J6(-3.5,0.5) J7(-2.5,0.5) J8(-1.5,0.5) J11(1.5,0.5) J12(2.5,0.5) J13(3.5,0.5) J14(4.5,0.5) J15(5.5,0.5) J16(6.5,0.5) J17(7.5,0.5) J18(8.5,0.5) K1(-8.5,-0.5) K2(-7.5,-0.5) K3(-6.5,-0.5) K4(-5.5,-0.5) K5(-4.5,-0.5) K6(-3.5,-0.5) K7(-2.5,-0.5) K8(-1.5,-0.5) K11(1.5,-0.5) K12(2.5,-0.5) K13(3.5,-0.5) K14(4.5,-0.5) K15(5.5,-0.5) K16(6.5,-0.5) K17(7.5,-0.5) K18(8.5,-0.5) L1(-8.5,-1.5) L2(-7.5,-1.5) L3(-6.5,-1.5) L4(-5.5,-1.5) L5(-4.5,-1.5) L6(-3.5,-1.5) L7(-2.5,-1.5) L8(-1.5,-1.5) L9(-0.5,-1.5) L10(0.5,-1.5) L11(1.5,-1.5) L12(2.5,-1.5) L13(3.5,-1.5) L14(4.5,-1.5) L15(5.5,-1.5) L16(6.5,-1.5) L17(7.5,-1.5) L18(8.5,-1.5) M1(-8.5,-2.5) M2(-7.5,-2.5) M3(-6.5,-2.5) M4(-5.5,-2.5) M5(-4.5,-2.5) M6(-3.5,-2.5) M7(-2.5,-2.5) M8(-1.5,-2.5) M9(-0.5,-2.5) M10(0.5,-2.5) M11(1.5,-2.5) M12(2.5,-2.5) M13(3.5,-2.5) M14(4.5,-2.5) M15(5.5,-2.5) M16(6.5,-2.5) M17(7.5,-2.5) M18(8.5,-2.5) N1(-8.5,-3.5) N2(-7.5,-3.5) N3(-6.5,-3.5) N4(-5.5,-3.5) N5(-4.5,-3.5) N6(-3.5,-3.5) N7(-2.5,-3.5) N8(-1.5,-3.5) N9(-0.5,-3.5) N10(0.5,-3.5) N11(1.5,-3.5) N12(2.5,-3.5) N13(3.5,-3.5) N14(4.5,-3.5) N15(5.5,-3.5) N16(6.5,-3.5) N17(7.5,-3.5) N18(8.5,-3.5) P1(-8.5,-4.5) P2(-7.5,-4.5) P3(-6.5,-4.5) P4(-5.5,-4.5) P5(-4.5,-4.5) P6(-3.5,-4.5) P7(-2.5,-4.5) P8(-1.5,-4.5) P9(-0.5,-4.5) P10(0.5,-4.5) P11(1.5,-4.5) P12(2.5,-4.5) P13(3.5,-4.5) P14(4.5,-4.5) P15(5.5,-4.5) P16(6.5,-4.5) P17(7.5,-4.5) P18(8.5,-4.5) R1(-8.5,-5.5) R2(-7.5,-5.5) R3(-6.5,-5.5) R4(-5.5,-5.5) R5(-4.5,-5.5) R6(-3.5,-5.5) R7(-2.5,-5.5) R8(-1.5,-5.5) R9(-0.5,-5.5) R10(0.5,-5.5) R11(1.5,-5.5) R12(2.5,-5.5) R13(3.5,-5.5) R14(4.5,-5.5) R15(5.5,-5.5) R16(6.5,-5.5) R17(7.5,-5.5) R18(8.5,-5.5) T1(-8.5,-6.5) T2(-7.5,-6.5) T3(-6.5,-6.5) T4(-5.5,-6.5) T5(-4.5,-6.5) T6(-3.5,-6.5) T7(-2.5,-6.5) T8(-1.5,-6.5) T9(-0.5,-6.5) T10(0.5,-6.5) T11(1.5,-6.5) T12(2.5,-6.5) T13(3.5,-6.5) T14(4.5,-6.5) T15(5.5,-6.5) T16(6.5,-6.5) T17(7.5,-6.5) T18(8.5,-6.5) U1(-8.5,-7.5) U2(-7.5,-7.5) U3(-6.5,-7.5) U4(-5.5,-7.5) U5(-4.5,-7.5) U6(-3.5,-7.5) U7(-2.5,-7.5) U8(-1.5,-7.5) U9(-0.5,-7.5) U10(0.5,-7.5) U11(1.5,-7.5) U12(2.5,-7.5) U13(3.5,-7.5) U14(4.5,-7.5) U15(5.5,-7.5) U16(6.5,-7.5) U17(7.5,-7.5) U18(8.5,-7.5) V1(-8.5,-8.5) V2(-7.5,-8.5) V3(-6.5,-8.5) V4(-5.5,-8.5) V5(-4.5,-8.5) V6(-3.5,-8.5) V7(-2.5,-8.5) V8(-1.5,-8.5) V9(-0.5,-8.5) V10(0.5,-8.5) V11(1.5,-8.5) V12(2.5,-8.5) V13(3.5,-8.5) V14(4.5,-8.5) V15(5.5,-8.5) V16(6.5,-8.5) V17(7.5,-8.5) V18(8.5,-8.5)
Top Overlay:
  circle w0.25: c-10.15,8.5 r0.125
  region: -8.5,9.5 -9.5,8.5 -9.5,9.5
  lines w0.2: -9.5,8.5 -8.5,9.5 ; -9.5,-9.5 9.5,-9.5 9.5,9.5 -9.5,9.5 -9.5,-9.5
Mechanical 13:
  lines w0.1: -9.5,-9.5 9.5,-9.5 9.5,9.5 -9.5,9.5 -9.5,-9.5
Mechanical 15:
  lines w0.1: -0.5,0 0.5,0 ; 0,-0.5 0,0.5 ; -10.5,-10.5 10.5,-10.5 10.5,10.5 -10.5,10.5 -10.5,-10.5
3D body: height 0, standoff 0, extent -9.5,-9.5 9.5,9.5

## BGA100P18X18-324 [mm] "BGA, 324-Leads, Body 19x19mm, Pitch 1mm"
height 1.78
pads (324):
  round 0.5 smd: A1(-8.5,8.5) A2(-7.5,8.5) A3(-6.5,8.5) A4(-5.5,8.5) A5(-4.5,8.5) A6(-3.5,8.5) A7(-2.5,8.5) A8(-1.5,8.5) A9(-0.5,8.5) A10(0.5,8.5) A11(1.5,8.5) A12(2.5,8.5) A13(3.5,8.5) A14(4.5,8.5) A15(5.5,8.5) A16(6.5,8.5) A17(7.5,8.5) A18(8.5,8.5) B1(-8.5,7.5) B2(-7.5,7.5) B3(-6.5,7.5) B4(-5.5,7.5) B5(-4.5,7.5) B6(-3.5,7.5) B7(-2.5,7.5) B8(-1.5,7.5) B9(-0.5,7.5) B10(0.5,7.5) B11(1.5,7.5) B12(2.5,7.5) B13(3.5,7.5) B14(4.5,7.5) B15(5.5,7.5) B16(6.5,7.5) B17(7.5,7.5) B18(8.5,7.5) C1(-8.5,6.5) C2(-7.5,6.5) C3(-6.5,6.5) C4(-5.5,6.5) C5(-4.5,6.5) C6(-3.5,6.5) C7(-2.5,6.5) C8(-1.5,6.5) C9(-0.5,6.5) C10(0.5,6.5) C11(1.5,6.5) C12(2.5,6.5) C13(3.5,6.5) C14(4.5,6.5) C15(5.5,6.5) C16(6.5,6.5) C17(7.5,6.5) C18(8.5,6.5) D1(-8.5,5.5) D2(-7.5,5.5) D3(-6.5,5.5) D4(-5.5,5.5) D5(-4.5,5.5) D6(-3.5,5.5) D7(-2.5,5.5) D8(-1.5,5.5) D9(-0.5,5.5) D10(0.5,5.5) D11(1.5,5.5) D12(2.5,5.5) D13(3.5,5.5) D14(4.5,5.5) D15(5.5,5.5) D16(6.5,5.5) D17(7.5,5.5) D18(8.5,5.5) E1(-8.5,4.5) E2(-7.5,4.5) E3(-6.5,4.5) E4(-5.5,4.5) E5(-4.5,4.5) E6(-3.5,4.5) E7(-2.5,4.5) E8(-1.5,4.5) E9(-0.5,4.5) E10(0.5,4.5) E11(1.5,4.5) E12(2.5,4.5) E13(3.5,4.5) E14(4.5,4.5) E15(5.5,4.5) E16(6.5,4.5) E17(7.5,4.5) E18(8.5,4.5) F1(-8.5,3.5) F2(-7.5,3.5) F3(-6.5,3.5) F4(-5.5,3.5) F5(-4.5,3.5) F6(-3.5,3.5) F7(-2.5,3.5) F8(-1.5,3.5) F9(-0.5,3.5) F10(0.5,3.5) F11(1.5,3.5) F12(2.5,3.5) F13(3.5,3.5) F14(4.5,3.5) F15(5.5,3.5) F16(6.5,3.5) F17(7.5,3.5) F18(8.5,3.5) G1(-8.5,2.5) G2(-7.5,2.5) G3(-6.5,2.5) G4(-5.5,2.5) G5(-4.5,2.5) G6(-3.5,2.5) G7(-2.5,2.5) G8(-1.5,2.5) G9(-0.5,2.5) G10(0.5,2.5) G11(1.5,2.5) G12(2.5,2.5) G13(3.5,2.5) G14(4.5,2.5) G15(5.5,2.5) G16(6.5,2.5) G17(7.5,2.5) G18(8.5,2.5) H1(-8.5,1.5) H2(-7.5,1.5) H3(-6.5,1.5) H4(-5.5,1.5) H5(-4.5,1.5) H6(-3.5,1.5) H7(-2.5,1.5) H8(-1.5,1.5) H9(-0.5,1.5) H10(0.5,1.5) H11(1.5,1.5) H12(2.5,1.5) H13(3.5,1.5) H14(4.5,1.5) H15(5.5,1.5) H16(6.5,1.5) H17(7.5,1.5) H18(8.5,1.5) J1(-8.5,0.5) J2(-7.5,0.5) J3(-6.5,0.5) J4(-5.5,0.5) J5(-4.5,0.5) J6(-3.5,0.5) J7(-2.5,0.5) J8(-1.5,0.5) J9(-0.5,0.5) J10(0.5,0.5) J11(1.5,0.5) J12(2.5,0.5) J13(3.5,0.5) J14(4.5,0.5) J15(5.5,0.5) J16(6.5,0.5) J17(7.5,0.5) J18(8.5,0.5) K1(-8.5,-0.5) K2(-7.5,-0.5) K3(-6.5,-0.5) K4(-5.5,-0.5) K5(-4.5,-0.5) K6(-3.5,-0.5) K7(-2.5,-0.5) K8(-1.5,-0.5) K9(-0.5,-0.5) K10(0.5,-0.5) K11(1.5,-0.5) K12(2.5,-0.5) K13(3.5,-0.5) K14(4.5,-0.5) K15(5.5,-0.5) K16(6.5,-0.5) K17(7.5,-0.5) K18(8.5,-0.5) L1(-8.5,-1.5) L2(-7.5,-1.5) L3(-6.5,-1.5) L4(-5.5,-1.5) L5(-4.5,-1.5) L6(-3.5,-1.5) L7(-2.5,-1.5) L8(-1.5,-1.5) L9(-0.5,-1.5) L10(0.5,-1.5) L11(1.5,-1.5) L12(2.5,-1.5) L13(3.5,-1.5) L14(4.5,-1.5) L15(5.5,-1.5) L16(6.5,-1.5) L17(7.5,-1.5) L18(8.5,-1.5) M1(-8.5,-2.5) M2(-7.5,-2.5) M3(-6.5,-2.5) M4(-5.5,-2.5) M5(-4.5,-2.5) M6(-3.5,-2.5) M7(-2.5,-2.5) M8(-1.5,-2.5) M9(-0.5,-2.5) M10(0.5,-2.5) M11(1.5,-2.5) M12(2.5,-2.5) M13(3.5,-2.5) M14(4.5,-2.5) M15(5.5,-2.5) M16(6.5,-2.5) M17(7.5,-2.5) M18(8.5,-2.5) N1(-8.5,-3.5) N2(-7.5,-3.5) N3(-6.5,-3.5) N4(-5.5,-3.5) N5(-4.5,-3.5) N6(-3.5,-3.5) N7(-2.5,-3.5) N8(-1.5,-3.5) N9(-0.5,-3.5) N10(0.5,-3.5) N11(1.5,-3.5) N12(2.5,-3.5) N13(3.5,-3.5) N14(4.5,-3.5) N15(5.5,-3.5) N16(6.5,-3.5) N17(7.5,-3.5) N18(8.5,-3.5) P1(-8.5,-4.5) P2(-7.5,-4.5) P3(-6.5,-4.5) P4(-5.5,-4.5) P5(-4.5,-4.5) P6(-3.5,-4.5) P7(-2.5,-4.5) P8(-1.5,-4.5) P9(-0.5,-4.5) P10(0.5,-4.5) P11(1.5,-4.5) P12(2.5,-4.5) P13(3.5,-4.5) P14(4.5,-4.5) P15(5.5,-4.5) P16(6.5,-4.5) P17(7.5,-4.5) P18(8.5,-4.5) R1(-8.5,-5.5) R2(-7.5,-5.5) R3(-6.5,-5.5) R4(-5.5,-5.5) R5(-4.5,-5.5) R6(-3.5,-5.5) R7(-2.5,-5.5) R8(-1.5,-5.5) R9(-0.5,-5.5) R10(0.5,-5.5) R11(1.5,-5.5) R12(2.5,-5.5) R13(3.5,-5.5) R14(4.5,-5.5) R15(5.5,-5.5) R16(6.5,-5.5) R17(7.5,-5.5) R18(8.5,-5.5) T1(-8.5,-6.5) T2(-7.5,-6.5) T3(-6.5,-6.5) T4(-5.5,-6.5) T5(-4.5,-6.5) T6(-3.5,-6.5) T7(-2.5,-6.5) T8(-1.5,-6.5) T9(-0.5,-6.5) T10(0.5,-6.5) T11(1.5,-6.5) T12(2.5,-6.5) T13(3.5,-6.5) T14(4.5,-6.5) T15(5.5,-6.5) T16(6.5,-6.5) T17(7.5,-6.5) T18(8.5,-6.5) U1(-8.5,-7.5) U2(-7.5,-7.5) U3(-6.5,-7.5) U4(-5.5,-7.5) U5(-4.5,-7.5) U6(-3.5,-7.5) U7(-2.5,-7.5) U8(-1.5,-7.5) U9(-0.5,-7.5) U10(0.5,-7.5) U11(1.5,-7.5) U12(2.5,-7.5) U13(3.5,-7.5) U14(4.5,-7.5) U15(5.5,-7.5) U16(6.5,-7.5) U17(7.5,-7.5) U18(8.5,-7.5) V1(-8.5,-8.5) V2(-7.5,-8.5) V3(-6.5,-8.5) V4(-5.5,-8.5) V5(-4.5,-8.5) V6(-3.5,-8.5) V7(-2.5,-8.5) V8(-1.5,-8.5) V9(-0.5,-8.5) V10(0.5,-8.5) V11(1.5,-8.5) V12(2.5,-8.5) V13(3.5,-8.5) V14(4.5,-8.5) V15(5.5,-8.5) V16(6.5,-8.5) V17(7.5,-8.5) V18(8.5,-8.5)
Top Overlay:
  circle w0.25: c-10.15,8.5 r0.125
  region: -8.5,9.5 -9.5,8.5 -9.5,9.5
  lines w0.2: -9.5,8.5 -8.5,9.5 ; -9.5,-9.5 9.5,-9.5 9.5,9.5 -9.5,9.5 -9.5,-9.5
Mechanical 13:
  lines w0.1: -9.5,-9.5 9.5,-9.5 9.5,9.5 -9.5,9.5 -9.5,-9.5
Mechanical 15:
  lines w0.1: -0.5,0 0.5,0 ; 0,-0.5 0,0.5 ; -10.5,-10.5 10.5,-10.5 10.5,10.5 -10.5,10.5 -10.5,-10.5
3D body: height 0, standoff 0, extent -9.5,-9.5 9.5,9.5

## BGA100P19X19-361 [mm] "BGA, 361-Leads, Body 21x21mm, Pitch 1mm"
height 3.5
pads (361):
  round 0.5 smd: A1(-9,9) A2(-8,9) A3(-7,9) A4(-6,9) A5(-5,9) A6(-4,9) A7(-3,9) A8(-2,9) A9(-1,9) A10(0,9) A11(1,9) A12(2,9) A13(3,9) A14(4,9) A15(5,9) A16(6,9) A17(7,9) A18(8,9) A19(9,9) B1(-9,8) B2(-8,8) B3(-7,8) B4(-6,8) B5(-5,8) B6(-4,8) B7(-3,8) B8(-2,8) B9(-1,8) B10(0,8) B11(1,8) B12(2,8) B13(3,8) B14(4,8) B15(5,8) B16(6,8) B17(7,8) B18(8,8) B19(9,8) C1(-9,7) C2(-8,7) C3(-7,7) C4(-6,7) C5(-5,7) C6(-4,7) C7(-3,7) C8(-2,7) C9(-1,7) C10(0,7) C11(1,7) C12(2,7) C13(3,7) C14(4,7) C15(5,7) C16(6,7) C17(7,7) C18(8,7) C19(9,7) D1(-9,6) D2(-8,6) D3(-7,6) D4(-6,6) D5(-5,6) D6(-4,6) D7(-3,6) D8(-2,6) D9(-1,6) D10(0,6) D11(1,6) D12(2,6) D13(3,6) D14(4,6) D15(5,6) D16(6,6) D17(7,6) D18(8,6) D19(9,6) E1(-9,5) E2(-8,5) E3(-7,5) E4(-6,5) E5(-5,5) E6(-4,5) E7(-3,5) E8(-2,5) E9(-1,5) E10(0,5) E11(1,5) E12(2,5) E13(3,5) E14(4,5) E15(5,5) E16(6,5) E17(7,5) E18(8,5) E19(9,5) F1(-9,4) F2(-8,4) F3(-7,4) F4(-6,4) F5(-5,4) F6(-4,4) F7(-3,4) F8(-2,4) F9(-1,4) F10(0,4) F11(1,4) F12(2,4) F13(3,4) F14(4,4) F15(5,4) F16(6,4) F17(7,4) F18(8,4) F19(9,4) G1(-9,3) G2(-8,3) G3(-7,3) G4(-6,3) G5(-5,3) G6(-4,3) G7(-3,3) G8(-2,3) G9(-1,3) G10(0,3) G11(1,3) G12(2,3) G13(3,3) G14(4,3) G15(5,3) G16(6,3) G17(7,3) G18(8,3) G19(9,3) H1(-9,2) H2(-8,2) H3(-7,2) H4(-6,2) H5(-5,2) H6(-4,2) H7(-3,2) H8(-2,2) H9(-1,2) H10(0,2) H11(1,2) H12(2,2) H13(3,2) H14(4,2) H15(5,2) H16(6,2) H17(7,2) H18(8,2) H19(9,2) J1(-9,1) J2(-8,1) J3(-7,1) J4(-6,1) J5(-5,1) J6(-4,1) J7(-3,1) J8(-2,1) J9(-1,1) J10(0,1) J11(1,1) J12(2,1) J13(3,1) J14(4,1) J15(5,1) J16(6,1) J17(7,1) J18(8,1) J19(9,1) K1(-9,0) K2(-8,0) K3(-7,0) K4(-6,0) K5(-5,0) K6(-4,0) K7(-3,0) K8(-2,0) K9(-1,0) K10(0,0) K11(1,0) K12(2,0) K13(3,0) K14(4,0) K15(5,0) K16(6,0) K17(7,0) K18(8,0) K19(9,0) L1(-9,-1) L2(-8,-1) L3(-7,-1) L4(-6,-1) L5(-5,-1) L6(-4,-1) L7(-3,-1) L8(-2,-1) L9(-1,-1) L10(0,-1) L11(1,-1) L12(2,-1) L13(3,-1) L14(4,-1) L15(5,-1) L16(6,-1) L17(7,-1) L18(8,-1) L19(9,-1) M1(-9,-2) M2(-8,-2) M3(-7,-2) M4(-6,-2) M5(-5,-2) M6(-4,-2) M7(-3,-2) M8(-2,-2) M9(-1,-2) M10(0,-2) M11(1,-2) M12(2,-2) M13(3,-2) M14(4,-2) M15(5,-2) M16(6,-2) M17(7,-2) M18(8,-2) M19(9,-2) N1(-9,-3) N2(-8,-3) N3(-7,-3) N4(-6,-3) N5(-5,-3) N6(-4,-3) N7(-3,-3) N8(-2,-3) N9(-1,-3) N10(0,-3) N11(1,-3) N12(2,-3) N13(3,-3) N14(4,-3) N15(5,-3) N16(6,-3) N17(7,-3) N18(8,-3) N19(9,-3) P1(-9,-4) P2(-8,-4) P3(-7,-4) P4(-6,-4) P5(-5,-4) P6(-4,-4) P7(-3,-4) P8(-2,-4) P9(-1,-4) P10(0,-4) P11(1,-4) P12(2,-4) P13(3,-4) P14(4,-4) P15(5,-4) P16(6,-4) P17(7,-4) P18(8,-4) P19(9,-4) R1(-9,-5) R2(-8,-5) R3(-7,-5) R4(-6,-5) R5(-5,-5) R6(-4,-5) R7(-3,-5) R8(-2,-5) R9(-1,-5) R10(0,-5) R11(1,-5) R12(2,-5) R13(3,-5) R14(4,-5) R15(5,-5) R16(6,-5) R17(7,-5) R18(8,-5) R19(9,-5) T1(-9,-6) T2(-8,-6) T3(-7,-6) T4(-6,-6) T5(-5,-6) T6(-4,-6) T7(-3,-6) T8(-2,-6) T9(-1,-6) T10(0,-6) T11(1,-6) T12(2,-6) T13(3,-6) T14(4,-6) T15(5,-6) T16(6,-6) T17(7,-6) T18(8,-6) T19(9,-6) U1(-9,-7) U2(-8,-7) U3(-7,-7) U4(-6,-7) U5(-5,-7) U6(-4,-7) U7(-3,-7) U8(-2,-7) U9(-1,-7) U10(0,-7) U11(1,-7) U12(2,-7) U13(3,-7) U14(4,-7) U15(5,-7) U16(6,-7) U17(7,-7) U18(8,-7) U19(9,-7) V1(-9,-8) V2(-8,-8) V3(-7,-8) V4(-6,-8) V5(-5,-8) V6(-4,-8) V7(-3,-8) V8(-2,-8) V9(-1,-8) V10(0,-8) V11(1,-8) V12(2,-8) V13(3,-8) V14(4,-8) V15(5,-8) V16(6,-8) V17(7,-8) V18(8,-8) V19(9,-8) W1(-9,-9) W2(-8,-9) W3(-7,-9) W4(-6,-9) W5(-5,-9) W6(-4,-9) W7(-3,-9) W8(-2,-9) W9(-1,-9) W10(0,-9) W11(1,-9) W12(2,-9) W13(3,-9) W14(4,-9) W15(5,-9) W16(6,-9) W17(7,-9) W18(8,-9) W19(9,-9)
Top Overlay:
  circle w0.25: c-11.15,9 r0.125
  region: -9.5,10.5 -10.5,9.5 -10.5,10.5
  lines w0.2: -10.5,9.5 -9.5,10.5 ; -10.5,-10.5 -10.5,10.5 10.5,10.5 10.5,-10.5 -10.5,-10.5
Mechanical 13:
  lines w0.1: -10.5,-10.5 -10.5,10.5 10.5,10.5 10.5,-10.5 -10.5,-10.5
Mechanical 15:
  lines w0.1: -0.5,0 0.5,0 ; 0,-0.5 0,0.5 ; -11.5,-11.5 -11.5,11.5 11.5,11.5 11.5,-11.5 -11.5,-11.5
3D body: height 0, standoff 0, extent -10.5,-10.5 10.5,10.5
